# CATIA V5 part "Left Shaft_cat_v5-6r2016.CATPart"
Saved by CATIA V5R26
Part number: Left hand shaft
Bounding box of the stored display mesh (mm): x 0 to 100, y -25 to 25, z -24.818 to 24.818
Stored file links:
  D:\_Deepak\CATIA\CATIA V5 2015 Parts Files\Tutorial Files\Tutorials\c16_catia_v5_6r2016_tut\CV joint\Left Shaft_cat_v5-6r2012.CATPart
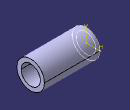
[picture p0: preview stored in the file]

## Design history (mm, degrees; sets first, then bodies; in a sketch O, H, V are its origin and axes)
Body1 (main body)
  Sketch1 on yz-plane, origin (0, 0, 0), H (0, 1, 0), V (0, 0, 1)
    circle A1 centre (0, 0) radius 25
    circle A2 centre (0, 0) radius 17.5
    radius A1 = 25
    radius A2 = 17.5
  Pad1: profile Sketch1, direction (1, 0, 0), length 100
  Sketch2 on end face of Pad1, origin (100, 0, 0), H (0, 1, 0), V (0, 0, 1)
    line L1 (5, 35) -> (5, -35)
    line L2 (5, -35) -> (-5, -35)
    line L3 (-5, -35) -> (-5, 35)
    line L4 (-5, 35) -> (5, 35)
    length L1 = 70
    length L4 = 10
    vertical: L1 V, L3 V
    horizontal: L2 H, L4 H
    equidistance: L1 L3 O, L2 L4 O
  Pad2: profile Sketch2, direction (-1, 0, 0), length 10
Current feature: Pad1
